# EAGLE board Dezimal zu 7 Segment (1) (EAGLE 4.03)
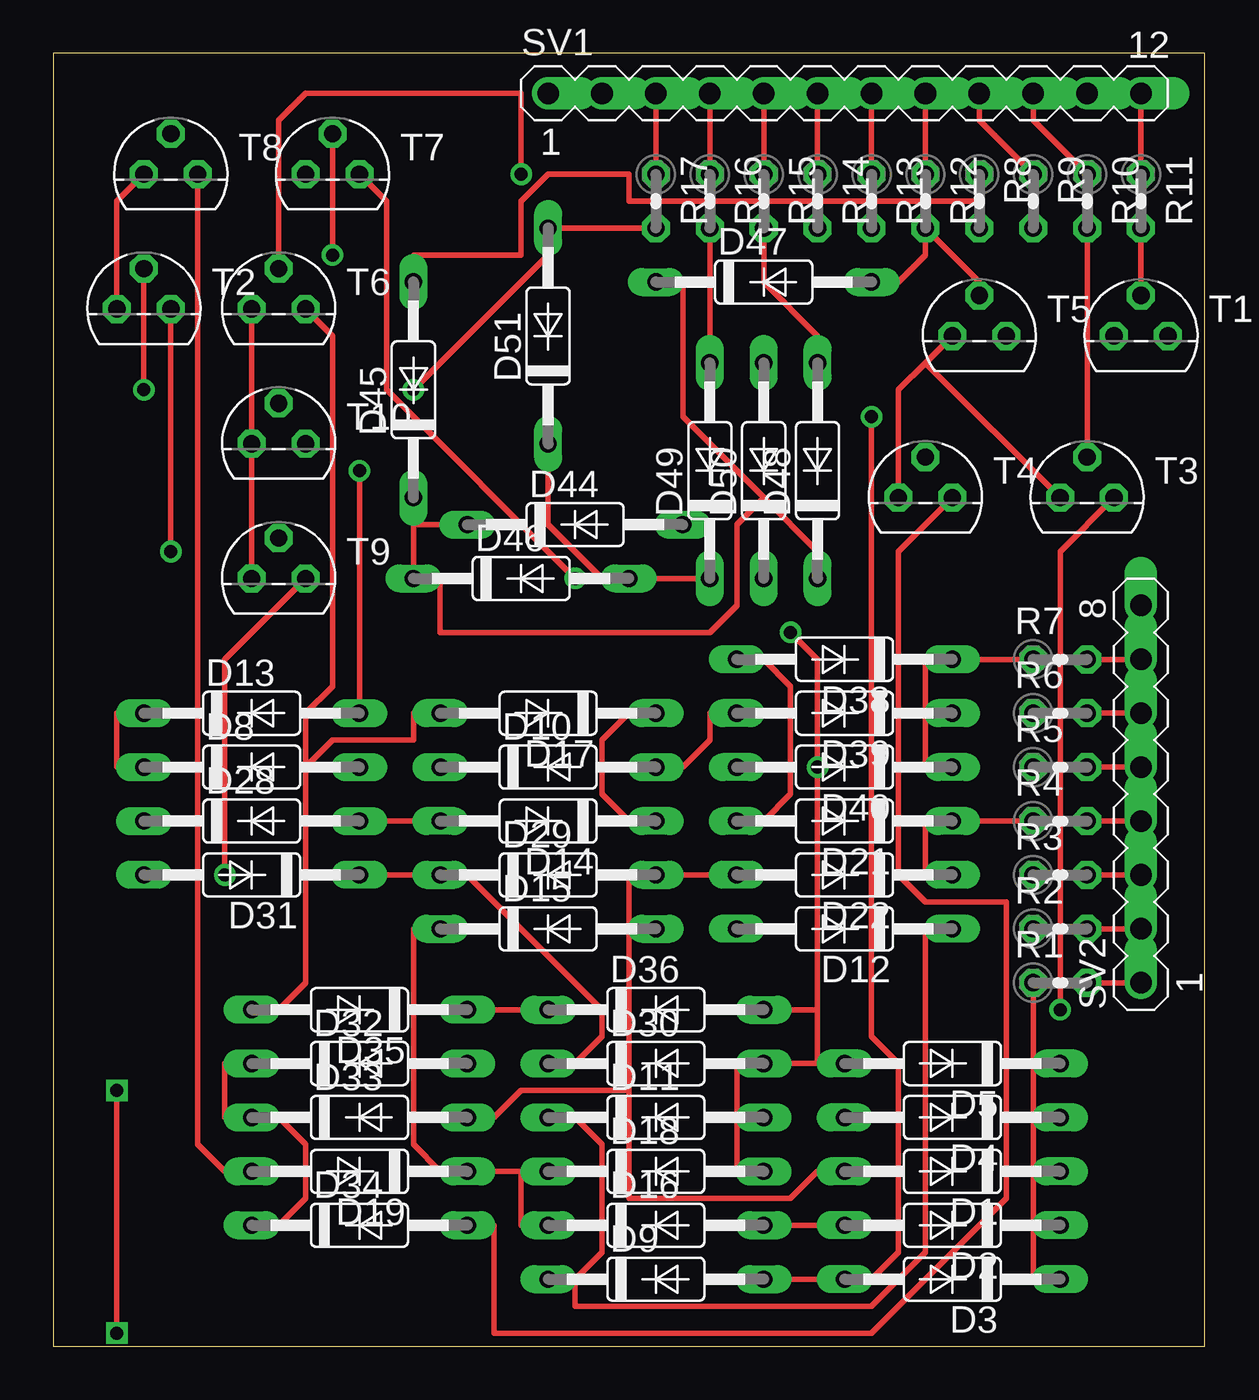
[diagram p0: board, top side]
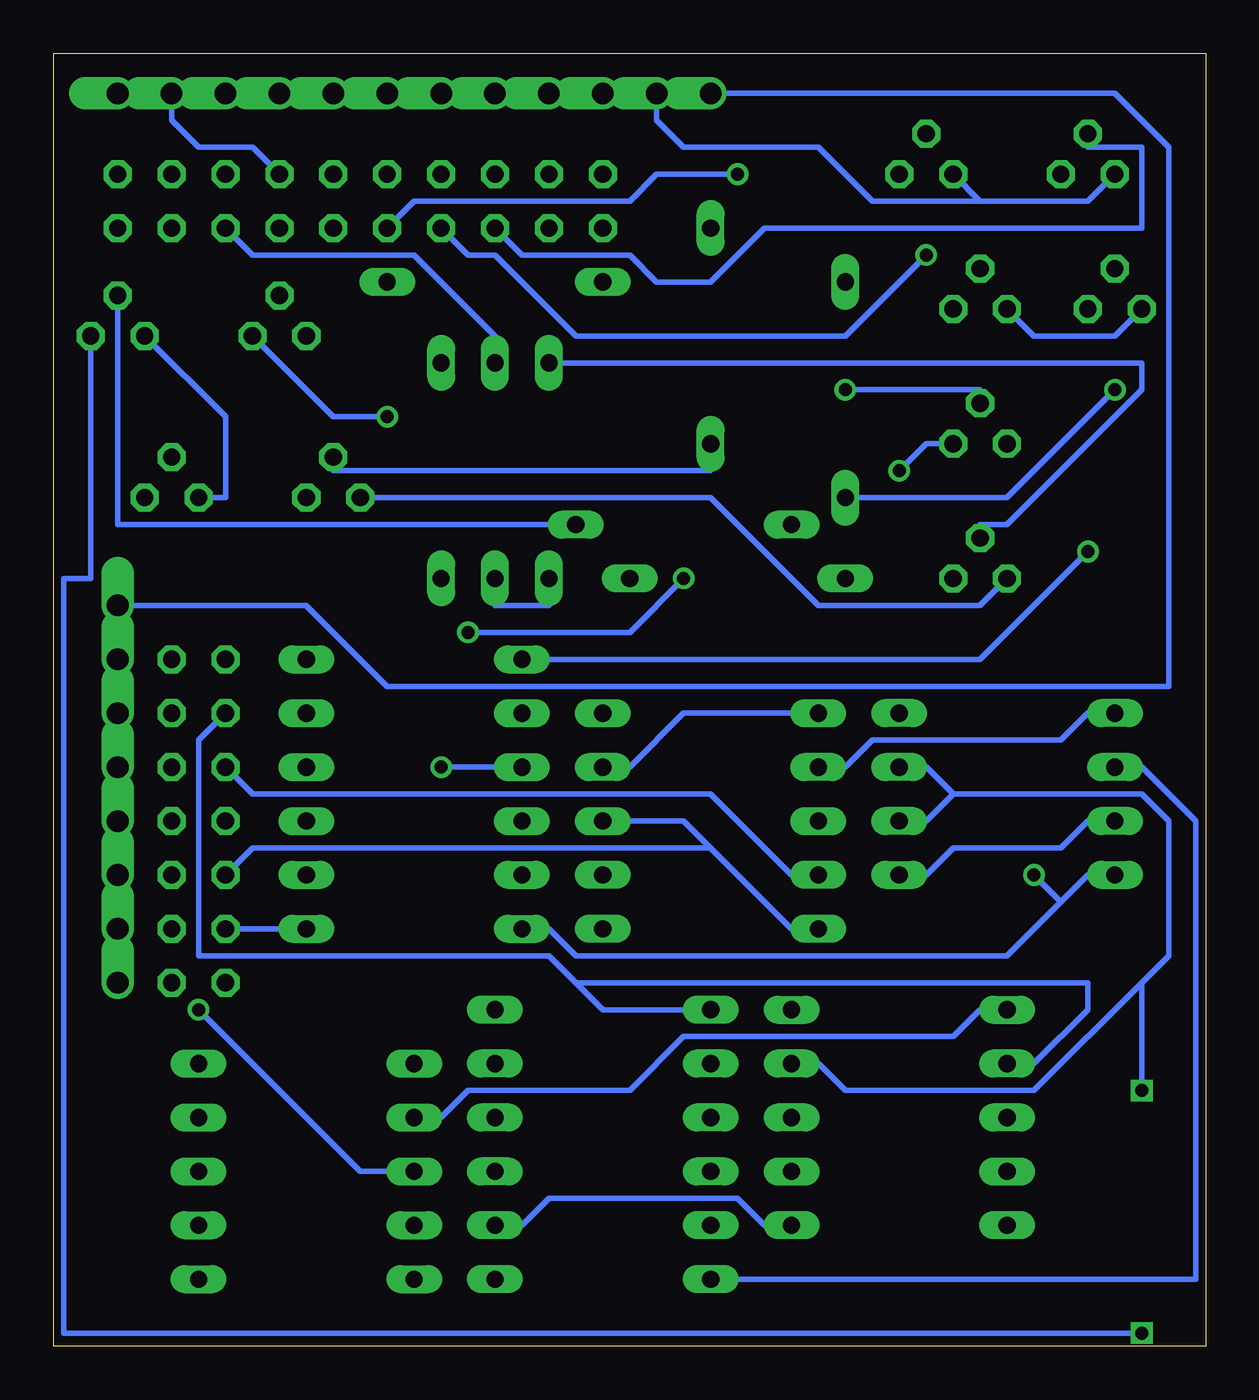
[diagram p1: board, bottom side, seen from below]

Size 54.28 x 60.95 mm. Coordinates in mm from the lower left corner, seen from the top.
Outline: 0,0 54.28,0 54.28,60.95 0,60.95 0,0
Copper layers used: Top, Bottom

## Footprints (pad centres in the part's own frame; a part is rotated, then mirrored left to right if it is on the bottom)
DO35-10 = drill 0.813 long: A 5.08,0; C -5.08,0
0204V = drill 0.813 octagon: 1 -1.27,0; 2 1.27,0
MA12-1 = drill 1.016 offset: 1 -13.97,0; 2 -11.43,0; 3 -8.89,0; 4 -6.35,0; 5 -3.81,0; 6 -1.27,0; 7 1.27,0; 8 3.81,0; 9 6.35,0; 10 8.89,0; 11 11.43,0; 12 13.97,0
MA08-1 = drill 1.016 offset: 1 -8.89,0; 2 -6.35,0; 3 -3.81,0; 4 -1.27,0; 5 1.27,0; 6 3.81,0; 7 6.35,0; 8 8.89,0
TO92 = drill 0.813 octagon: 1 1.27,0; 2 0,1.905; 3 -1.27,0

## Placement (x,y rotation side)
D1  1N4148  [DO35-10]  42.38,8.25 180 top
D2  1N4148  [DO35-10]  42.38,5.71 180 top
D3  1N4148  [DO35-10]  42.38,3.17 180 top
D4  1N4148  [DO35-10]  42.38,10.79 180 top
D5  1N4148  [DO35-10]  42.38,13.33 180 top
D8  1N4148  [DO35-10]  9.36,27.3 0 top
D9  1N4148  [DO35-10]  28.41,3.17 0 top
D10  1N4148  [DO35-10]  23.33,27.3 0 top
D11  1N4148  [DO35-10]  28.41,10.79 0 top
D12  1N4148  [DO35-10]  37.3,19.68 180 top
D13  1N4148  [DO35-10]  9.36,29.84 0 top
D14  1N4148  [DO35-10]  23.33,24.76 180 top
D15  1N4148  [DO35-10]  23.33,19.68 0 top
D16  1N4148  [DO35-10]  28.41,5.71 0 top
D17  1N4148  [DO35-10]  23.33,29.84 180 top
D18  1N4148  [DO35-10]  28.41,8.25 0 top
D19  1N4148  [DO35-10]  14.44,8.25 180 top
D21  1N4148  [DO35-10]  37.3,24.76 180 top
D22  1N4148  [DO35-10]  37.3,22.22 180 top
D28  1N4148  [DO35-10]  9.36,24.76 0 top
D29  1N4148  [DO35-10]  23.33,22.22 0 top
D30  1N4148  [DO35-10]  28.41,13.33 0 top
D31  1N4148  [DO35-10]  9.36,22.22 180 top
D32  1N4148  [DO35-10]  14.44,13.33 0 top
D33  1N4148  [DO35-10]  14.44,10.79 0 top
D34  1N4148  [DO35-10]  14.44,5.71 0 top
D35  1N4148  [DO35-10]  14.44,15.87 180 top
D36  1N4148  [DO35-10]  28.41,15.87 0 top
D38  1N4148  [DO35-10]  37.3,32.38 180 top
D39  1N4148  [DO35-10]  37.3,29.84 180 top
D40  1N4148  [DO35-10]  37.3,27.3 180 top
D44  1N4148  [DO35-10]  24.6,38.73 0 top
D45  1N4148  [DO35-10]  16.98,45.08 90 top
D46  1N4148  [DO35-10]  22.06,36.19 0 top
D47  1N4148  [DO35-10]  33.49,50.16 0 top
D48  1N4148  [DO35-10]  36.03,41.27 90 top
D49  1N4148  [DO35-10]  30.95,41.27 90 top
D50  1N4148  [DO35-10]  33.49,41.27 90 top
D51  1N4148  [DO35-10]  23.33,47.62 90 top
R1  [0204V]  47.46,17.14 0 top
R2  [0204V]  47.46,19.68 0 top
R3  [0204V]  47.46,22.22 0 top
R4  [0204V]  47.46,24.76 0 top
R5  [0204V]  47.46,27.3 0 top
R6  [0204V]  47.46,29.84 0 top
R7  [0204V]  47.46,32.38 0 top
R8  [0204V]  43.65,53.97 270 top
R9  [0204V]  46.19,53.97 270 top
R10  [0204V]  48.73,53.97 270 top
R11  [0204V]  51.27,53.97 270 top
R12  [0204V]  41.11,53.97 270 top
R13  [0204V]  38.57,53.97 270 top
R14  [0204V]  36.03,53.97 270 top
R15  [0204V]  33.49,53.97 270 top
R16  [0204V]  30.95,53.97 270 top
R17  [0204V]  28.41,53.97 270 top
SV1  [MA12-1]  37.3,59.05 0 top
SV2  [MA08-1]  51.27,26.03 90 top
T1  BC547  [TO92]  51.27,47.62 0 top
T2  BC547  [TO92]  4.28,48.89 0 top
T3  BC547  [TO92]  48.73,40 0 top
T4  BC547  [TO92]  41.11,40 0 top
T5  BC547  [TO92]  43.65,47.62 0 top
T6  BC547  [TO92]  10.63,48.89 0 top
T7  BC547  [TO92]  13.17,55.24 0 top
T8  BC547  [TO92]  5.55,55.24 0 top
T9  BC547  [TO92]  10.63,36.19 0 top
T10  BC547  [TO92]  10.63,42.54 0 top

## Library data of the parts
D1-D5 D8-D19 D21 D22 D28-D36 D38-D40 D44-D51 = diode
R1-R17 = rcl
SV1 SV2 = con-lstb
T1-T10 = transistor-npn

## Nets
N$1: D21.A D38.A T2.1
N$2: D1.C D2.C D3.C D4.C D5.C R1.1
N$3: D44.A R11.2 T1.2
N$4: D44.C D45.C D46.C D47.C D48.C T2.2
N$5: D3.A D9.A T5.1
N$6: D4.A D10.A D17.A D35.A D39.A T6.1
N$7: D8.C D9.C D10.C D11.C D12.C D13.C R2.1
N$8: D14.C D15.C D16.C D17.C D18.C D19.C R3.1
N$9: D21.C D22.C R4.1
N$10: D28.C D29.C D30.C D31.C R5.1
N$11: D5.A D11.A D18.A D30.A D36.A D40.A T7.1
N$12: D32.C D33.C D34.C D35.C D36.C R6.1
N$13: D38.C D39.C D40.C R7.1
N$14: D8.A D14.A D28.A D32.A T1.1
N$15: D45.A R8.2
N$16: D50.A R9.2
N$17: R1.2 SV2.1
N$18: D1.A D15.A D22.A D29.A D33.A T3.1
N$19: D48.A R15.2 T8.2
N$20: R10.2 T3.2
N$21: D19.A T8.1
N$22: R2.2 SV2.2
N$23: D46.A D49.C D50.C D51.C T4.2
N$24: R13.2 T6.2
N$25: D2.A D16.A D34.A T4.1
N$26: D49.A R16.2 T9.2
N$27: D12.A D31.A T9.1
N$28: R14.2 T7.2
N$29: D47.A R12.2 T5.2
N$30: R3.2 SV2.3
N$31: SV1.2 T1.3 T2.3 T3.3 T4.3 T5.3 T6.3 T7.3 T8.3 T9.3 T10.3
N$32: D51.A R17.2 T10.2
N$33: D13.A T10.1
N$34: R4.2 SV2.4
N$35: R5.2 SV2.5
N$36: R11.1 SV1.12
N$37: R8.1 SV1.11
N$38: R10.1 SV1.10
N$39: R9.1 SV1.9
N$40: R12.1 SV1.8
N$41: R13.1 SV1.7
N$42: R14.1 SV1.6
N$43: R15.1 SV1.5
N$44: R16.1 SV1.4
N$45: R17.1 SV1.3
N$46: SV1.1 SV2.8
N$47: R6.2 SV2.6
N$48: R7.2 SV2.7

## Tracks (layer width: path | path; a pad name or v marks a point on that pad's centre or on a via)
N$1  (via drill 0.61)
  Top 0.254: D21.A 33.49,24.76 34.76,26.03 34.76,31.11 33.49,32.38 D38.A | v5.55,37.46 T2.1
  Bottom 0.254: v5.55,37.46 10.63,32.38 D38.A
N$2
  Top 0.254: 46.19,5.71 46.19,3.17 D3.C | 46.19,8.25 46.19,10.79 | 46.19,10.79 46.19,13.33 | 46.19,10.79 D4.C | 46.19,13.33 R1.1 | 46.19,13.33 D5.C | 46.19,5.71 46.19,8.25 | 46.19,5.71 D2.C | 46.19,8.25 D1.C
N$3
  Top 0.254: T1.2 R11.2
  Bottom 0.254: D44.A 51.27,38.73 T1.2
N$4  (via drill 0.61)
  Top 0.254: 33.49,40 29.68,43.81 29.68,50.16 D47.C | 33.49,40 36.03,37.46 D48.C | 16.98,38.73 D46.C 18.25,36.19 18.25,33.65 30.95,33.65 32.22,34.92 32.22,38.73 33.49,40 | v4.28,45.08 T2.2 | 16.98,38.73 D44.C | D45.C 16.98,38.73
  Bottom 0.254: v4.28,45.08 9.36,40 D45.C
N$5  (via drill 0.61)
  Top 0.254: D9.A D3.A 38.57,3.17 39.84,4.44 39.84,13.33 38.57,14.6 v38.57,43.81
  Bottom 0.254: T5.1 41.11,43.81 v38.57,43.81
N$6
  Top 0.254: D10.A 29.68,27.3 30.95,28.57 30.95,29.84 D39.A | 11.9,27.3 11.9,17.14 10.63,15.87 D35.A | 11.9,27.3 13.17,28.57 16.98,28.57 16.98,29.84 D17.A | T6.1 13.17,47.62 13.17,31.11 11.9,29.84 11.9,27.3
  Bottom 0.254: D4.A 36.03,10.79 34.76,12.06 27.14,12.06 24.6,14.6 11.9,14.6 10.63,15.87 D35.A | D10.A 27.14,27.3 24.6,29.84 D17.A
N$7
  Top 0.254: D8.C 3.01,27.3 3.01,29.84 D13.C | 24.6,3.17 25.87,4.44 25.87,9.52 24.6,10.79 D11.C | 24.6,3.17 24.6,1.9 38.57,1.9 41.11,4.44 41.11,19.68 D12.C | D9.C 24.6,3.17
  Bottom 0.254: D10.C 16.98,27.3 15.71,28.57 6.82,28.57 5.55,29.84 D13.C | D12.C R2.1 | D8.C 3.01,27.3 0.47,24.76 0.47,3.17 D9.C
N$8
  Top 0.254: 22.06,8.25 D19.C 18.25,8.25 16.98,9.52 16.98,19.68 D15.C | 22.06,8.25 22.06,5.71 D16.C | 22.06,8.25 D18.C | D17.C 27.14,29.84 25.87,28.57 25.87,26.03 27.14,24.76 D14.C
  Bottom 0.254: 23.33,23.49 24.6,24.76 D14.C | 23.33,23.49 19.52,19.68 D15.C | R3.1 44.92,23.49 23.33,23.49
N$9
  Top 0.254: D22.C 41.11,22.22 41.11,24.76 D21.C R4.1
N$10
  Top 0.254: D31.C D29.C 19.52,22.22 25.87,15.87 25.87,14.6 24.6,13.33 D30.C
  Bottom 0.254: D28.C 5.55,24.76 6.82,23.49 11.9,23.49 13.17,22.22 D31.C | R5.1 44.92,26.03 23.33,26.03 19.52,22.22 D29.C
N$11  (via drill 0.61)
  Top 0.254: 32.22,10.79 32.22,8.25 D18.A | 36.03,13.33 D30.A 32.22,13.33 32.22,10.79 | 36.03,13.33 36.03,15.87 | 36.03,15.87 v36.03,27.3 36.03,32.38 v34.76,33.65 | 36.03,13.33 D5.A | T7.1 15.71,53.97 15.71,45.08 v24.6,36.19 | 36.03,15.87 D36.A | 32.22,10.79 D11.A
  Bottom 0.254: v36.03,27.3 D40.A | v24.6,36.19 27.14,33.65 v34.76,33.65
N$12
  Top 0.254: D34.C 10.63,5.71 11.9,6.98 11.9,9.52 10.63,10.79 D33.C 8.09,10.79 8.09,13.33 D32.C | D36.C D35.C
  Bottom 0.254: R6.1 47.46,28.57 47.46,18.41 30.95,18.41 29.68,17.14 | 29.68,17.14 28.41,15.87 D36.C | 29.68,17.14 5.55,17.14 5.55,15.87 8.09,13.33 D32.C
N$13
  Top 0.254: 41.11,29.84 41.11,27.3 D40.C | 41.11,29.84 41.11,32.38 D38.C R7.1 | 41.11,29.84 D39.C
N$14  (via drill 0.61)
  Top 0.254: v3.01,0.63 v3.01,12.06 | D28.A D14.A D28.A
  Bottom 0.254: 3.01,17.14 8.09,12.06 16.98,12.06 18.25,13.33 D32.A | 11.9,26.03 13.17,27.3 D8.A | T1.1 52.54,36.19 53.81,36.19 53.81,0.63 v3.01,0.63 | v3.01,12.06 3.01,17.14 | 3.01,17.14 1.74,18.41 1.74,24.76 3.01,26.03 11.9,26.03 | 11.9,26.03 13.17,24.76 D28.A
N$15
  Top 0.254: R8.2 43.65,53.97 27.14,53.97 27.14,55.24 23.33,55.24 22.06,53.97 22.06,51.43 16.98,51.43 D45.A
N$16
  Bottom 0.254: R9.2 44.92,51.43 37.3,51.43 33.49,47.62 D50.A
N$17
  Top 0.254: R1.2 SV2.1
N$18  (via drill 0.61)
  Top 0.254: D22.A D29.A 27.14,22.22 27.14,19.68 | 27.14,12.06 22.06,12.06 20.79,10.79 D33.A | 27.14,12.06 27.14,19.68 | 27.14,12.06 27.14,6.98 34.76,6.98 36.03,8.25 D1.A | T3.1 47.46,37.46 v47.46,15.87 | 27.14,19.68 D15.A
  Bottom 0.254: v47.46,15.87 39.84,8.25 D1.A
N$19
  Top 0.254: R15.2 33.49,50.16 36.03,47.62 D48.A
  Bottom 0.254: R15.2 32.22,51.43 27.14,51.43 25.87,50.16 23.33,50.16 20.79,52.7 3.01,52.7 3.01,56.51 5.55,56.51 T8.2
N$20
  Top 0.254: T3.2 R10.2
N$21
  Top 0.254: T8.1 6.82,9.52 8.09,8.25 D19.A
N$22
  Top 0.254: R2.2 SV2.2
N$23
  Top 0.254: D49.C D46.A 25.87,36.19 23.33,38.73 D51.C
  Bottom 0.254: D50.C 33.49,34.92 30.95,34.92 D49.C | T4.2 41.11,41.27 23.33,41.27 D51.C
N$24  (via drill 0.61)
  Top 0.254: v22.06,55.24 22.06,59.05 11.9,59.05 10.63,57.78 T6.2
  Bottom 0.254: v22.06,55.24 25.87,55.24 27.14,53.97 37.3,53.97 R13.2
N$25
  Top 0.254: D16.A D2.A | T4.1 39.84,37.46 39.84,22.22 41.11,20.95 44.92,20.95 44.92,6.98 38.57,0.63 20.79,0.63 20.79,5.71 D34.A
  Bottom 0.254: D34.A 20.79,5.71 22.06,6.98 30.95,6.98 32.22,5.71 D16.A
N$26
  Top 0.254: D49.A R16.2
  Bottom 0.254: D49.A 3.01,46.35 3.01,45.08 9.36,38.73 10.63,38.73 T9.2
N$27  (via drill 0.61)
  Top 0.254: T9.1 8.09,32.38 v8.09,22.22
  Bottom 0.254: 6.82,20.95 9.36,18.41 29.68,18.41 30.95,19.68 D12.A | 6.82,20.95 5.55,22.22 D31.A | 6.82,20.95 v8.09,22.22
N$28  (via drill 0.61)
  Top 0.254: v13.17,51.43 T7.2
  Bottom 0.254: v13.17,51.43 16.98,47.62 29.68,47.62 33.49,51.43 34.76,51.43 R14.2
N$29
  Top 0.254: T5.2 43.65,50.16 R12.2 41.11,51.43 39.84,50.16 D47.A
N$30
  Top 0.254: R3.2 SV2.3
N$31
  Top 0.254: T4.3 39.84,45.08 41.11,46.35 | 41.11,46.35 T5.3 | 41.11,46.35 T3.3 | T9.3 T10.3 T6.3 | T2.3 3.01,53.97 T8.3
  Bottom 0.254: T1.3 46.19,43.81 46.19,40 T3.3 | 10.63,53.97 T7.3 | 10.63,53.97 5.55,53.97 T8.3 | 10.63,53.97 15.71,53.97 18.25,56.51 24.6,56.51 25.87,57.78 SV1.2 | T6.3 8.09,47.62 4.28,47.62 T2.3 | T4.3 23.33,40 18.25,34.92 10.63,34.92 T9.3
N$32  (via drill 0.61)
  Top 0.254: v16.98,45.08 23.33,51.43 D51.A R17.2
  Bottom 0.254: v16.98,45.08 10.63,45.08 T10.2
N$33  (via drill 0.61)
  Top 0.254: D13.A v14.44,41.27
  Bottom 0.254: v14.44,41.27 13.17,42.54 T10.1
N$34
  Top 0.254: R4.2 SV2.4
N$35
  Top 0.254: R5.2 SV2.5
N$36
  Top 0.254: R11.1 SV1.12
N$37
  Bottom 0.254: R8.1 44.92,56.51 47.46,56.51 48.73,57.78 SV1.11
N$38
  Top 0.254: R10.1 46.19,57.78 SV1.10
N$39
  Top 0.254: R9.1 43.65,57.78 SV1.9
N$40
  Top 0.254: R12.1 SV1.8
N$41
  Top 0.254: R13.1 SV1.7
N$42
  Top 0.254: R14.1 SV1.6
N$43
  Top 0.254: R15.1 SV1.5
N$44
  Top 0.254: R16.1 SV1.4
N$45
  Top 0.254: R17.1 SV1.3
N$46
  Bottom 0.254: SV1.1 4.28,59.05 1.74,56.51 1.74,31.11 38.57,31.11 42.38,34.92 SV2.8
N$47
  Top 0.254: R6.2 SV2.6
N$48
  Top 0.254: R7.2 SV2.7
